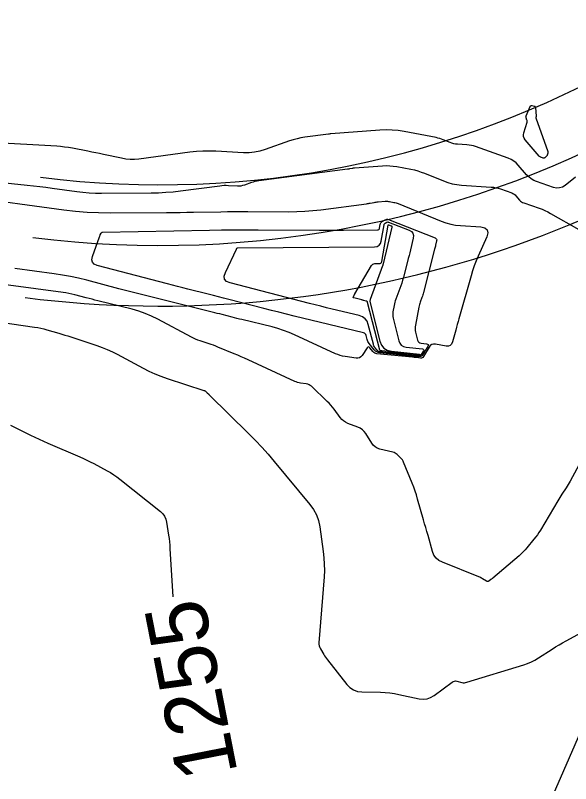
# Model space of a CAD drawing. Extents: x 658976 to 668726, y 639543 to 647196.
# Drawn here: x 661412.3 to 661467.2, y 641412.7 to 641488.7 of the extents above; entities that cross this region are included whole.
import ezdxf

# ---------------------------------------------------------------- set-up
doc = ezdxf.new("R2010")
doc.units = 0
for name, color, linetype in [('Ex_Contour Labels', 7, 'Continuous'), ('Ex_Major Contours', 7, 'Continuous'), ('Ex_Minor Contours', 7, 'Continuous'), ('R_Water', 7, 'Continuous')]:
    doc.layers.add(name, color=color, linetype=linetype)

msp = doc.modelspace()

# ---------------------------------------------------------------- linework, layer by layer
at = {"layer": 'Ex_Major Contours'}
for points in [[(661464.858, 641474.801), (661464.837, 641474.763), (661464.809, 641474.728), (661464.776, 641474.698), (661464.632, 641474.584), (661464.595, 641474.561), (661464.556, 641474.548), (661464.515, 641474.547), (661464.472, 641474.556), (661464.258, 641474.63), (661464.21, 641474.65), (661464.165, 641474.676), (661464.125, 641474.707), (661464.088, 641474.745), (661462.708, 641476.36), (661462.601, 641476.517), (661462.541, 641476.685), (661462.528, 641476.863), (661462.562, 641477.05), (661462.879, 641478.1), (661462.89, 641478.153), (661462.893, 641478.205), (661462.887, 641478.257), (661462.871, 641478.309), (661462.793, 641478.515), (661462.778, 641478.567), (661462.774, 641478.618), (661462.78, 641478.67), (661462.796, 641478.721), (661463.174, 641479.646), (661463.202, 641479.695), (661463.239, 641479.726), (661463.286, 641479.74), (661463.343, 641479.737), (661463.586, 641479.689), (661463.64, 641479.671), (661463.68, 641479.64), (661463.705, 641479.597), (661463.716, 641479.541), (661463.769, 641478.7), (661463.769, 641478.685), (661463.769, 641478.67), (661463.767, 641478.655), (661463.765, 641478.64), (661463.753, 641478.581), (661463.752, 641478.566), (661463.752, 641478.551), (661463.754, 641478.537), (661463.758, 641478.522), (661464.924, 641475.205), (661464.936, 641475.161), (661464.941, 641475.116), (661464.938, 641475.071), (661464.929, 641475.026), (661464.874, 641474.843)], [(661451.44, 641467.286), (661451.586, 641467.111), (661451.646, 641466.891), (661451.621, 641466.626), (661451.348, 641465.478), (661451.279, 641465.191), (661451.209, 641464.905), (661451.138, 641464.618), (661451.066, 641464.333), (661450.731, 641463.025), (661450.656, 641462.746), (661450.574, 641462.47), (661450.486, 641462.196), (661450.39, 641461.924), (661449.906, 641460.598), (661449.854, 641460.447), (661449.809, 641460.295), (661449.77, 641460.141), (661449.737, 641459.985), (661449.618, 641459.358), (661449.597, 641459.201), (661449.592, 641459.045), (661449.605, 641458.89), (661449.635, 641458.735), (661450.188, 641456.491), (661450.288, 641456.231), (661450.446, 641456.036), (661450.66, 641455.906), (661450.931, 641455.842), (661452.528, 641455.673), (661452.609, 641455.653), (661452.653, 641455.614), (661452.658, 641455.555), (661452.626, 641455.477), (661452.419, 641455.129), (661452.361, 641455.054), (661452.291, 641455.004), (661452.209, 641454.978), (661452.114, 641454.978), (661449.917, 641455.232), (661449.743, 641455.252), (661449.569, 641455.27), (661449.395, 641455.289), (661449.22, 641455.306), (661448.353, 641455.39), (661448.268, 641455.406), (661448.191, 641455.438), (661448.123, 641455.485), (661448.063, 641455.547), (661447.838, 641455.828), (661447.786, 641455.9), (661447.743, 641455.976), (661447.708, 641456.057), (661447.681, 641456.142), (661447.18, 641458.092), (661447.056, 641458.412), (661446.865, 641458.666), (661446.609, 641458.852), (661446.287, 641458.972), (661443.618, 641459.619), (661443.055, 641459.757), (661442.492, 641459.896), (661441.93, 641460.039), (661441.369, 641460.183), (661433.514, 641462.218), (661433.169, 641462.362), (661432.975, 641462.578), (661432.934, 641462.865), (661433.044, 641463.222), (661434.149, 641465.559), (661434.154, 641465.57), (661434.16, 641465.58), (661434.166, 641465.591), (661434.172, 641465.602), (661434.197, 641465.644), (661434.204, 641465.653), (661434.212, 641465.66), (661434.222, 641465.664), (661434.234, 641465.665), (661447.791, 641465.779), (661448.049, 641465.816), (661448.248, 641465.924), (661448.388, 641466.102), (661448.467, 641466.351), (661448.751, 641467.96), (661448.764, 641468.004), (661448.784, 641468.043), (661448.813, 641468.076), (661448.85, 641468.104), (661449.014, 641468.204), (661449.055, 641468.223), (661449.098, 641468.232), (661449.141, 641468.23), (661449.185, 641468.218), (661451.208, 641467.417)]]:
    msp.add_lwpolyline(points, close=True, dxfattribs=at)
msp.add_lwpolyline([(661411.81, 641448.122), (661413.785, 641447.145), (661414.21, 641446.939), (661414.637, 641446.738), (661415.067, 641446.543), (661415.499, 641446.355), (661418.665, 641444.998), (661419.01, 641444.846), (661419.352, 641444.686), (661419.69, 641444.518), (661420.025, 641444.344), (661421.356, 641443.629), (661421.684, 641443.443), (661422.002, 641443.243), (661422.312, 641443.029), (661422.611, 641442.801), (661426.623, 641439.599), (661426.853, 641439.38), (661427.031, 641439.131), (661427.158, 641438.853), (661427.233, 641438.545), (661427.433, 641437.252), (661427.479, 641436.929), (661427.517, 641436.604), (661427.548, 641436.279), (661427.572, 641435.953), (661427.867, 641431.17)], dxfattribs=at)
at = {"layer": 'Ex_Minor Contours'}
for points in [[(661467.671, 641472.671), (661466.635, 641471.854), (661466.369, 641471.688), (661466.09, 641471.6), (661465.798, 641471.59), (661465.492, 641471.658), (661463.824, 641472.228), (661463.54, 641472.346), (661463.279, 641472.498), (661463.042, 641472.684), (661462.827, 641472.904), (661462.016, 641473.854), (661461.802, 641474.074), (661461.564, 641474.262), (661461.304, 641474.416), (661461.022, 641474.537), (661457.793, 641475.682), (661457.584, 641475.748), (661457.373, 641475.8), (661457.158, 641475.837), (661456.94, 641475.859), (661455.994, 641475.923), (661455.811, 641475.943), (661455.632, 641475.976), (661455.455, 641476.024), (661455.282, 641476.087), (661454.597, 641476.364), (661454.424, 641476.429), (661454.249, 641476.485), (661454.071, 641476.533), (661453.891, 641476.571), (661450.712, 641477.173), (661450.121, 641477.266), (661449.527, 641477.319), (661448.932, 641477.334), (661448.334, 641477.31), (661443.484, 641476.958), (661443.464, 641476.956), (661443.444, 641476.953), (661443.424, 641476.95), (661443.404, 641476.947), (661443.324, 641476.931), (661443.304, 641476.927), (661443.284, 641476.924), (661443.264, 641476.921), (661443.244, 641476.918), (661440.914, 641476.612), (661440.521, 641476.55), (661440.134, 641476.468), (661439.751, 641476.365), (661439.373, 641476.242), (661436.99, 641475.394), (661436.464, 641475.235), (661435.93, 641475.129), (661435.388, 641475.078), (661434.839, 641475.08), (661432.102, 641475.222), (661431.462, 641475.241), (661430.824, 641475.231), (661430.186, 641475.191), (661429.549, 641475.122), (661424.498, 641474.46), (661424.066, 641474.422), (661423.637, 641474.421), (661423.208, 641474.457), (661422.781, 641474.53), (661420.99, 641474.914), (661420.607, 641474.995), (661420.224, 641475.074), (661419.84, 641475.151), (661419.456, 641475.226), (661417.919, 641475.523), (661417.534, 641475.591), (661417.148, 641475.646), (661416.759, 641475.687), (661416.37, 641475.715), (661402.641, 641476.479)], [(661385.487, 641474.849), (661413.462, 641471.874), (661414.074, 641471.807), (661414.687, 641471.735), (661415.298, 641471.659), (661415.91, 641471.579), (661418.354, 641471.248), (661418.966, 641471.177), (661419.579, 641471.126), (661420.193, 641471.097), (661420.809, 641471.089), (661425.703, 641471.113), (661426.429, 641471.128), (661427.153, 641471.166), (661427.876, 641471.226), (661428.597, 641471.309), (661432.498, 641471.821), (661432.709, 641471.843), (661432.92, 641471.857), (661433.131, 641471.86), (661433.343, 641471.854), (661434.248, 641471.807), (661434.43, 641471.806), (661434.609, 641471.823), (661434.786, 641471.858), (661434.96, 641471.91), (661435.651, 641472.156), (661435.825, 641472.213), (661436.002, 641472.261), (661436.18, 641472.299), (661436.361, 641472.327), (661445.117, 641473.475), (661445.176, 641473.483), (661445.234, 641473.492), (661445.293, 641473.502), (661445.351, 641473.513), (661445.584, 641473.56), (661445.643, 641473.57), (661445.701, 641473.579), (661445.76, 641473.586), (661445.819, 641473.591), (661448.591, 641473.793), (661448.944, 641473.807), (661449.296, 641473.798), (661449.647, 641473.766), (661449.996, 641473.712), (661451.392, 641473.448), (661451.738, 641473.373), (661452.08, 641473.282), (661452.416, 641473.174), (661452.748, 641473.049), (661454.626, 641472.29), (661455.053, 641472.136), (661455.488, 641472.018), (661455.931, 641471.935), (661456.382, 641471.886), (661459.315, 641471.687), (661459.554, 641471.663), (661459.789, 641471.622), (661460.021, 641471.566), (661460.25, 641471.494), (661461.36, 641471.1), (661461.481, 641471.048), (661461.593, 641470.982), (661461.694, 641470.901), (661461.786, 641470.807), (661462.135, 641470.399), (661462.227, 641470.305), (661462.329, 641470.225), (661462.441, 641470.16), (661462.563, 641470.109), (661464.073, 641469.593), (661464.365, 641469.486), (661464.65, 641469.366), (661464.929, 641469.232), (661465.202, 641469.086), (661468.009, 641467.495)], [(661407.385, 641470.747), (661417.088, 641469.436), (661418.229, 641469.302), (661419.372, 641469.208), (661420.517, 641469.154), (661421.665, 641469.14), (661427.22, 641469.167), (661427.891, 641469.172), (661428.562, 641469.178), (661429.233, 641469.188), (661429.904, 641469.199), (661432.588, 641469.249), (661433.259, 641469.26), (661433.93, 641469.266), (661434.601, 641469.268), (661435.272, 641469.267), (661439.324, 641469.244), (661440.115, 641469.253), (661440.904, 641469.288), (661441.691, 641469.351), (661442.477, 641469.44), (661446.99, 641470.032), (661447.088, 641470.046), (661447.185, 641470.061), (661447.282, 641470.078), (661447.378, 641470.096), (661447.765, 641470.173), (661447.861, 641470.19), (661447.958, 641470.205), (661448.056, 641470.217), (661448.154, 641470.225), (661448.848, 641470.276), (661448.956, 641470.28), (661449.065, 641470.277), (661449.173, 641470.267), (661449.281, 641470.251), (661449.71, 641470.169), (661449.817, 641470.146), (661449.922, 641470.118), (661450.026, 641470.085), (661450.128, 641470.047), (661454.395, 641468.321), (661454.861, 641468.154), (661455.336, 641468.024), (661455.819, 641467.933), (661456.311, 641467.881), (661458.297, 641467.746), (661458.707, 641467.659), (661458.941, 641467.468), (661459.002, 641467.171), (661458.888, 641466.768), (661458.041, 641464.852), (661457.841, 641464.378), (661457.658, 641463.898), (661457.492, 641463.411), (661457.343, 641462.919), (661456.13, 641458.657), (661456.051, 641458.38), (661455.974, 641458.103), (661455.899, 641457.825), (661455.824, 641457.548), (661455.509, 641456.364), (661455.422, 641456.157), (661455.289, 641456.022), (661455.11, 641455.957), (661454.885, 641455.962), (661453.821, 641456.141), (661453.624, 641456.149), (661453.452, 641456.102), (661453.306, 641456.001), (661453.185, 641455.845), (661452.635, 641454.918), (661452.579, 641454.845), (661452.511, 641454.797), (661452.43, 641454.772), (661452.338, 641454.771), (661451.946, 641454.816), (661451.848, 641454.828), (661451.75, 641454.838), (661451.651, 641454.848), (661451.553, 641454.858), (661448.027, 641455.2), (661447.914, 641455.221), (661447.812, 641455.263), (661447.721, 641455.326), (661447.641, 641455.409), (661447.343, 641455.781), (661447.269, 641455.851), (661447.198, 641455.872), (661447.128, 641455.845), (661447.061, 641455.77), (661446.561, 641455.028), (661446.445, 641454.895), (661446.309, 641454.807), (661446.153, 641454.765), (661445.976, 641454.77), (661444.88, 641454.93), (661444.638, 641454.974), (661444.4, 641455.035), (661444.168, 641455.113), (661443.941, 641455.208), (661439.895, 641457.073), (661439.35, 641457.308), (661438.796, 641457.516), (661438.233, 641457.697), (661437.66, 641457.851), (661434.684, 641458.572), (661434.439, 641458.632), (661434.195, 641458.693), (661433.95, 641458.755), (661433.706, 641458.817), (661432.729, 641459.071), (661432.485, 641459.133), (661432.24, 641459.196), (661431.996, 641459.257), (661431.751, 641459.318), (661425.684, 641460.819), (661424.888, 641461.017), (661424.094, 641461.219), (661423.3, 641461.424), (661422.506, 641461.632), (661419.336, 641462.471), (661418.54, 641462.668), (661417.74, 641462.84), (661416.935, 641462.986), (661416.124, 641463.106), (661412.217, 641463.624)], [(661468.217, 641444.604), (661467.128, 641442.595), (661467.036, 641442.429), (661466.941, 641442.265), (661466.843, 641442.103), (661466.742, 641441.943), (661466.332, 641441.305), (661466.23, 641441.145), (661466.129, 641440.985), (661466.03, 641440.823), (661465.932, 641440.661), (661464.199, 641437.768), (661464.052, 641437.534), (661463.898, 641437.305), (661463.735, 641437.082), (661463.563, 641436.864), (661462.861, 641436.007), (661462.682, 641435.797), (661462.493, 641435.596), (661462.295, 641435.403), (661462.089, 641435.22), (661459.503, 641433.02), (661459.454, 641432.979), (661459.404, 641432.94), (661459.352, 641432.901), (661459.3, 641432.864), (661459.089, 641432.719), (661459.036, 641432.692), (661458.983, 641432.681), (661458.929, 641432.689), (661458.875, 641432.713), (661458.472, 641432.957), (661458.385, 641433.007), (661458.297, 641433.053), (661458.207, 641433.095), (661458.115, 641433.134), (661454.504, 641434.576), (661454.16, 641434.756), (661453.882, 641434.997), (661453.672, 641435.298), (661453.528, 641435.659), (661453.086, 641437.223), (661452.976, 641437.614), (661452.865, 641438.005), (661452.754, 641438.396), (661452.642, 641438.787), (661452.058, 641440.835), (661451.938, 641441.233), (661451.808, 641441.627), (661451.667, 641442.017), (661451.515, 641442.404), (661450.667, 641444.482), (661450.615, 641444.594), (661450.552, 641444.698), (661450.478, 641444.795), (661450.393, 641444.884), (661450.034, 641445.227), (661449.94, 641445.306), (661449.838, 641445.371), (661449.729, 641445.421), (661449.612, 641445.458), (661448.31, 641445.777), (661448.067, 641445.86), (661447.854, 641445.984), (661447.671, 641446.148), (661447.517, 641446.353), (661446.927, 641447.305), (661446.776, 641447.512), (661446.598, 641447.686), (661446.393, 641447.828), (661446.161, 641447.937), (661445.163, 641448.315), (661444.937, 641448.42), (661444.733, 641448.553), (661444.55, 641448.715), (661444.39, 641448.905), (661443.792, 641449.725), (661443.639, 641449.926), (661443.476, 641450.12), (661443.305, 641450.306), (661443.126, 641450.485), (661441.554, 641451.979), (661441.443, 641452.07), (661441.323, 641452.141), (661441.192, 641452.192), (661441.052, 641452.223), (661440.473, 641452.308), (661440.329, 641452.334), (661440.189, 641452.37), (661440.052, 641452.416), (661439.917, 641452.473), (661435.289, 641454.606), (661434.952, 641454.759), (661434.613, 641454.909), (661434.273, 641455.055), (661433.931, 641455.198), (661432.307, 641455.866), (661432.091, 641455.953), (661431.872, 641456.035), (661431.653, 641456.114), (661431.431, 641456.188), (661430.543, 641456.477), (661430.323, 641456.554), (661430.107, 641456.641), (661429.895, 641456.737), (661429.688, 641456.843), (661426.36, 641458.63), (661425.752, 641458.932), (661425.128, 641459.196), (661424.489, 641459.419), (661423.834, 641459.603), (661420.434, 641460.444), (661420.148, 641460.515), (661419.862, 641460.588), (661419.576, 641460.661), (661419.291, 641460.736), (661418.15, 641461.038), (661417.864, 641461.109), (661417.576, 641461.171), (661417.286, 641461.223), (661416.994, 641461.266), (661402.966, 641463.125)], [(661402.242, 641459.571), (661414.186, 641457.835), (661414.492, 641457.786), (661414.797, 641457.725), (661415.099, 641457.655), (661415.398, 641457.574), (661416.593, 641457.229), (661416.891, 641457.141), (661417.188, 641457.051), (661417.485, 641456.957), (661417.78, 641456.861), (661420.339, 641456.017), (661420.859, 641455.832), (661421.369, 641455.626), (661421.871, 641455.398), (661422.362, 641455.147), (661424.906, 641453.781), (661425.486, 641453.486), (661426.077, 641453.218), (661426.679, 641452.976), (661427.293, 641452.761), (661430.934, 641451.576), (661430.971, 641451.561), (661431.006, 641451.543), (661431.039, 641451.521), (661431.07, 641451.495), (661431.207, 641451.365), (661431.227, 641451.347), (661431.247, 641451.328), (661431.267, 641451.31), (661431.288, 641451.292), (661431.37, 641451.221), (661431.39, 641451.202), (661431.41, 641451.184), (661431.43, 641451.165), (661431.45, 641451.146), (661435.371, 641447.285), (661436.022, 641446.627), (661436.656, 641445.953), (661437.274, 641445.264), (661437.874, 641444.559), (661441.412, 641440.295), (661441.771, 641439.798), (661442.053, 641439.266), (661442.256, 641438.7), (661442.381, 641438.1), (661442.726, 641435.629), (661442.796, 641435.011), (661442.832, 641434.392), (661442.835, 641433.772), (661442.804, 641433.15), (661442.304, 641426.628), (661442.304, 641426.468), (661442.327, 641426.313), (661442.374, 641426.164), (661442.445, 641426.02), (661442.775, 641425.456), (661442.86, 641425.316), (661442.95, 641425.18), (661443.044, 641425.047), (661443.143, 641424.917), (661445.054, 641422.499), (661445.361, 641422.182), (661445.713, 641421.953), (661446.108, 641421.811), (661446.547, 641421.758), (661448.39, 641421.723), (661448.85, 641421.703), (661449.307, 641421.661), (661449.761, 641421.597), (661450.213, 641421.511), (661452.213, 641421.078), (661452.61, 641421.033), (661452.988, 641421.071), (661453.348, 641421.193), (661453.69, 641421.399), (661455.481, 641422.733), (661455.587, 641422.796), (661455.698, 641422.832), (661455.815, 641422.841), (661455.936, 641422.823), (661456.434, 641422.695), (661456.558, 641422.672), (661456.682, 641422.666), (661456.805, 641422.678), (661456.928, 641422.707), (661462.558, 641424.442), (661462.938, 641424.573), (661463.306, 641424.73), (661463.662, 641424.911), (661464.007, 641425.118), (661465.363, 641425.993), (661465.703, 641426.209), (661466.048, 641426.418), (661466.397, 641426.621), (661466.749, 641426.817), (661470.195, 641428.692)]]:
    msp.add_lwpolyline(points, dxfattribs=at)
for points in [[(661453.869, 641466.609), (661453.922, 641466.546), (661453.944, 641466.466), (661453.935, 641466.37), (661453.836, 641465.953), (661453.811, 641465.849), (661453.786, 641465.746), (661453.76, 641465.642), (661453.734, 641465.538), (661452.64, 641461.261), (661452.607, 641461.139), (661452.571, 641461.017), (661452.532, 641460.897), (661452.49, 641460.778), (661452.316, 641460.302), (661452.275, 641460.182), (661452.239, 641460.061), (661452.208, 641459.939), (661452.182, 641459.815), (661451.845, 641458.037), (661451.82, 641457.859), (661451.816, 641457.681), (661451.83, 641457.505), (661451.864, 641457.328), (661452.059, 641456.534), (661452.105, 641456.418), (661452.175, 641456.33), (661452.271, 641456.272), (661452.393, 641456.243), (661452.931, 641456.186), (661453.04, 641456.159), (661453.098, 641456.107), (661453.105, 641456.029), (661453.062, 641455.925), (661452.619, 641455.178), (661452.51, 641455.038), (661452.379, 641454.944), (661452.225, 641454.896), (661452.048, 641454.895), (661451.101, 641455.005), (661450.88, 641455.03), (661450.659, 641455.054), (661450.438, 641455.076), (661450.217, 641455.098), (661448.325, 641455.282), (661448.162, 641455.313), (661448.014, 641455.374), (661447.883, 641455.464), (661447.767, 641455.584), (661447.254, 641456.226), (661447.192, 641456.311), (661447.141, 641456.402), (661447.099, 641456.497), (661447.068, 641456.598), (661446.962, 641457.009), (661446.926, 641457.102), (661446.871, 641457.176), (661446.796, 641457.23), (661446.703, 641457.265), (661439.842, 641458.928), (661439.093, 641459.111), (661438.344, 641459.297), (661437.596, 641459.486), (661436.849, 641459.678), (661433.378, 641460.578), (661432.874, 641460.708), (661432.369, 641460.836), (661431.863, 641460.963), (661431.358, 641461.089), (661429.334, 641461.59), (661428.829, 641461.716), (661428.324, 641461.844), (661427.819, 641461.974), (661427.315, 641462.107), (661420.38, 641463.942), (661420.088, 641464.066), (661419.913, 641464.252), (661419.856, 641464.501), (661419.918, 641464.813), (661420.605, 641466.777), (661420.622, 641466.823), (661420.64, 641466.868), (661420.659, 641466.913), (661420.679, 641466.957), (661420.763, 641467.134), (661420.787, 641467.172), (661420.818, 641467.2), (661420.857, 641467.217), (661420.902, 641467.224), (661431.462, 641467.421), (661432.67, 641467.44), (661433.878, 641467.451), (661435.086, 641467.456), (661436.294, 641467.452), (661442.361, 641467.418), (661442.952, 641467.416), (661443.543, 641467.416), (661444.133, 641467.418), (661444.724, 641467.421), (661448.085, 641467.449), (661448.168, 641467.461), (661448.231, 641467.496), (661448.275, 641467.553), (661448.301, 641467.632), (661448.366, 641467.998), (661448.389, 641468.081), (661448.427, 641468.154), (661448.481, 641468.216), (661448.55, 641468.268), (661448.857, 641468.454), (661448.934, 641468.491), (661449.013, 641468.507), (661449.094, 641468.504), (661449.177, 641468.481), (661453.786, 641466.657)], [(661449.479, 641467.836), (661449.502, 641467.808), (661449.512, 641467.773), (661449.508, 641467.731), (661448.645, 641464.1), (661448.641, 641464.081), (661448.637, 641464.063), (661448.632, 641464.045), (661448.627, 641464.026), (661448.609, 641463.953), (661448.604, 641463.935), (661448.598, 641463.916), (661448.592, 641463.898), (661448.586, 641463.881), (661447.374, 641460.563), (661447.369, 641460.548), (661447.365, 641460.533), (661447.361, 641460.517), (661447.358, 641460.502), (661447.346, 641460.44), (661447.344, 641460.424), (661447.343, 641460.409), (661447.344, 641460.393), (661447.347, 641460.378), (661448.316, 641456.447), (661448.472, 641456.044), (661448.716, 641455.742), (661449.049, 641455.541), (661449.469, 641455.441), (661452.233, 641455.148), (661452.243, 641455.146), (661452.249, 641455.141), (661452.249, 641455.133), (661452.245, 641455.124), (661452.219, 641455.079), (661452.212, 641455.07), (661452.203, 641455.064), (661452.193, 641455.06), (661452.181, 641455.06), (661448.507, 641455.485), (661448.479, 641455.488), (661448.451, 641455.491), (661448.381, 641455.498), (661448.375, 641455.499), (661448.368, 641455.502), (661448.363, 641455.506), (661448.358, 641455.51), (661448.34, 641455.533), (661448.336, 641455.539), (661448.333, 641455.545), (661448.33, 641455.551), (661448.328, 641455.558), (661447.115, 641460.273), (661447.095, 641460.323), (661447.065, 641460.363), (661447.025, 641460.393), (661446.974, 641460.411), (661446.751, 641460.466), (661446.695, 641460.479), (661446.64, 641460.493), (661446.584, 641460.507), (661446.528, 641460.521), (661445.75, 641460.723), (661445.716, 641460.737), (661445.696, 641460.759), (661445.692, 641460.787), (661445.703, 641460.823), (661445.777, 641460.978), (661445.796, 641461.017), (661445.816, 641461.055), (661445.836, 641461.093), (661445.858, 641461.131), (661447.506, 641463.925), (661447.566, 641464.006), (661447.64, 641464.063), (661447.727, 641464.098), (661447.827, 641464.11), (661448.253, 641464.114), (661448.348, 641464.128), (661448.422, 641464.168), (661448.473, 641464.234), (661448.503, 641464.325), (661449.137, 641467.921), (661449.139, 641467.927), (661449.141, 641467.932), (661449.145, 641467.936), (661449.15, 641467.94), (661449.171, 641467.953), (661449.177, 641467.955), (661449.182, 641467.957), (661449.188, 641467.956), (661449.194, 641467.955), (661449.442, 641467.856)]]:
    msp.add_lwpolyline(points, close=True, dxfattribs=at)
at = {"layer": 'R_Water'}
msp.add_line((661431.238, 641332.446), (661498.605, 641488.168), dxfattribs=at)
for radius, end in [(94, 336.60619), (100, 336.60619), (106, 312.82532)]:
    msp.add_arc((661426.55, 641565.912), radius, 262.80026, end, dxfattribs=at)

# ---------------------------------------------------------------- texts
at = {"layer": 'Ex_Contour Labels'}
msp.add_text('1255', height=6, rotation=101.04437, dxfattribs=at).set_placement((661434.278, 641413.742))

doc.saveas('drawing.dxf')
